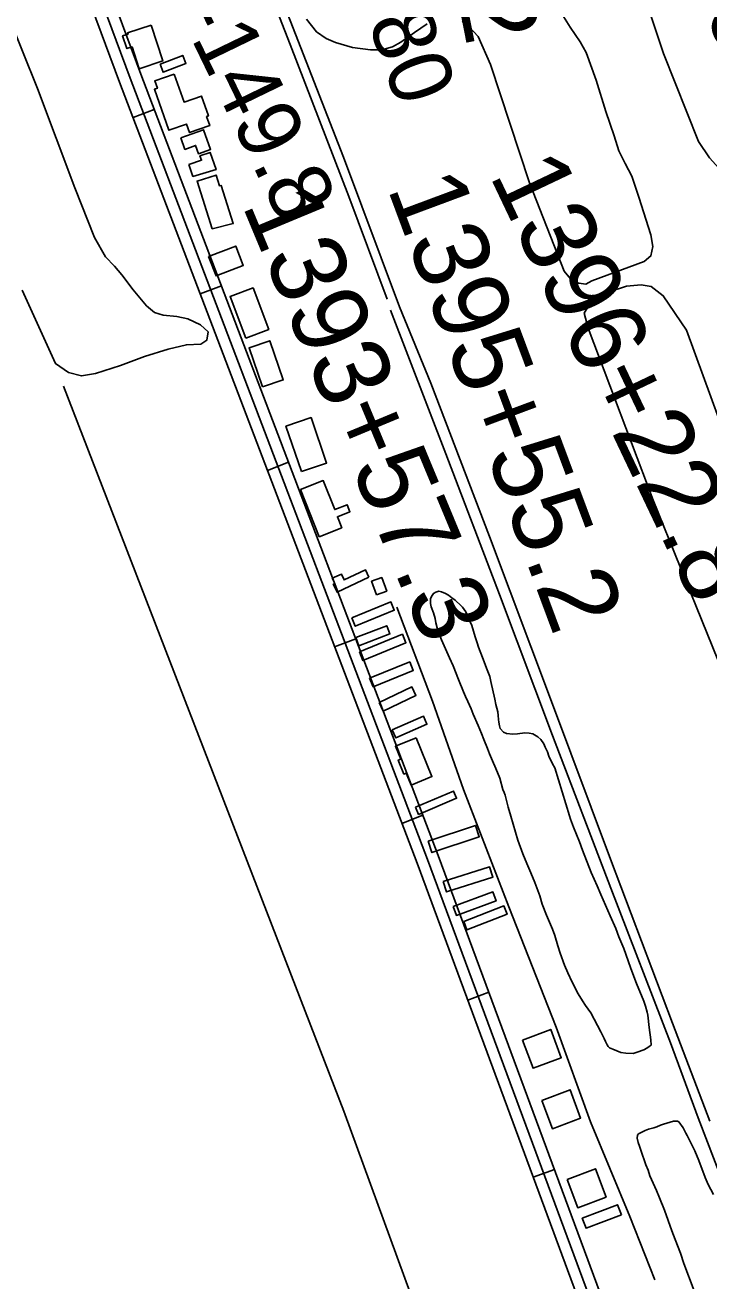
# Model space of a CAD drawing. Extents: x 3445503 to 3483459, y 540493 to 566012.
# Drawn here: x 3474080 to 3474986, y 547604 to 549267 of the extents above; entities that cross this region are included whole.
import ezdxf

# ---------------------------------------------------------------- set-up
doc = ezdxf.new("R2010")
doc.units = 0
for name, color, linetype in [('V-BLDG-OTLN', 7, 'Continuous'), ('V-DTCH-CNTR', 7, 'Continuous'), ('V-RIVR-RANG-IDEN', 7, 'Continuous'), ('V-ROAD-CNTR', 7, 'Continuous'), ('V-SITE-VEGE', 7, 'Continuous'), ('V-SURV-IDEN', 7, 'Continuous'), ('V-TOPO-SHOR', 7, 'Continuous')]:
    doc.layers.add(name, color=color, linetype=linetype)

msp = doc.modelspace()

# ---------------------------------------------------------------- linework, layer by layer
at = {"layer": 'V-BLDG-OTLN'}
for points in [[(3474247.1, 549266.8), (3474262.8, 549219.6), (3474231.5, 549209.2), (3474221.9, 549238), (3474215.1, 549235.8), (3474209.5, 549252.7), (3474216.6, 549255), (3474216.1, 549256.5)], [(3474259, 549215.1), (3474289.1, 549226.7), (3474293.2, 549216.1), (3474263.1, 549204.5)], [(3474277.8, 549202), (3474290.8, 549164.9), (3474313.8, 549173), (3474323.1, 549146.6), (3474320.7, 549145.7), (3474324.8, 549133.9), (3474298.1, 549124.5), (3474294.1, 549135.8), (3474270.5, 549127.6), (3474251.5, 549181.9), (3474255.5, 549183.3), (3474252.1, 549192.9)], [(3474286.6, 549117.7), (3474316.6, 549128.4), (3474325.9, 549102.4), (3474309.9, 549096.6), (3474306, 549107.5), (3474292, 549102.4)], [(3474297.2, 549082.2), (3474313.9, 549088), (3474311.9, 549093.7), (3474325.3, 549098.4), (3474333.3, 549075.6), (3474302.6, 549066.5)], [(3474328.1, 548997.2), (3474308.1, 549060.4), (3474333.2, 549068.4), (3474337.7, 549054.1), (3474339.8, 549054.7), (3474355.9, 549004.2)], [(3474323.2, 548960.4), (3474359.3, 548974.3), (3474369.2, 548948.7), (3474333.1, 548934.8)], [(3474372.4, 548852.5), (3474351.7, 548907.6), (3474382.2, 548919), (3474402.9, 548863.9)], [(3474394.7, 548787.8), (3474376.8, 548839.6), (3474404.2, 548849), (3474422.1, 548797.2)], [(3474446.1, 548675.7), (3474425.6, 548735.8), (3474458.9, 548747.2), (3474479.5, 548687.1)], [(3474469.7, 548589.5), (3474445, 548652), (3474475.2, 548663.9), (3474490.4, 548625.4), (3474506.8, 548631.9), (3474510.5, 548622.5), (3474493.9, 548615.9), (3474499.6, 548601.3)], [(3474535.5, 548535.8), (3474493.4, 548516), (3474488.4, 548526.6), (3474490.3, 548527.5), (3474487, 548534.4), (3474499.1, 548540.1), (3474502.7, 548532.4), (3474530.9, 548545.7)], [(3474545.8, 548512.5), (3474539.1, 548530.5), (3474552.5, 548535.5), (3474559.2, 548517.5)], [(3474512.8, 548482.2), (3474564.6, 548503.2), (3474569.1, 548492.1), (3474517.4, 548471)], [(3474518.1, 548455.9), (3474559.2, 548471.6), (3474563.3, 548460.7), (3474522.2, 548445.1)], [(3474523, 548437), (3474579.8, 548460.3), (3474584.5, 548449), (3474527.6, 548425.6)], [(3474536.4, 548402.3), (3474589.6, 548423.8), (3474594.2, 548412.5), (3474541, 548390.9)], [(3474549, 548370), (3474592.4, 548390.7), (3474597.8, 548379.4), (3474554.4, 548358.6)], [(3474566.5, 548333.9), (3474607.7, 548351.9), (3474612.4, 548341.1), (3474571.2, 548323.2)], [(3474598.3, 548323.1), (3474619, 548271.8), (3474591.4, 548260.7), (3474585, 548276.6), (3474581.8, 548275.3), (3474574.4, 548293.7), (3474577.6, 548295), (3474570.7, 548312)], [(3474597.3, 548231.2), (3474647.7, 548252.8), (3474651.7, 548243.3), (3474601.3, 548221.7)], [(3474613.8, 548186.4), (3474676.7, 548207.3), (3474681.7, 548192.2), (3474618.9, 548171.2)], [(3474634, 548132.8), (3474695.4, 548152.4), (3474699.7, 548138.9), (3474638.3, 548119.3)], [(3474647, 548099.9), (3474699.7, 548119.2), (3474704, 548107.2), (3474651.4, 548088)], [(3474661.1, 548080), (3474714.2, 548100.6), (3474718.5, 548089.7), (3474665.3, 548069.1)], [(3474738.7, 547923.1), (3474752.8, 547885.7), (3474790.2, 547899.7), (3474776.2, 547937.2)], [(3474764.4, 547843.1), (3474778.4, 547805.7), (3474815.9, 547819.8), (3474801.8, 547857.2)], [(3474798, 547738.5), (3474812, 547701.1), (3474849.5, 547715.2), (3474835.4, 547752.6)], [(3474869.8, 547691.8), (3474823.1, 547673.9), (3474818.1, 547687), (3474864.8, 547704.9)]]:
    msp.add_lwpolyline(points, close=True, dxfattribs=at)
at = {"layer": 'V-DTCH-CNTR'}
msp.add_lwpolyline([(3474987.1, 547815.8), (3474937.6, 547945.4), (3474855.2, 548162.5), (3474777.1, 548371.5), (3474695.1, 548589.8), (3474617.7, 548792.8), (3474576.2, 548893.8), (3474502, 549092.1), (3474410.2, 549327.9), (3474326.6, 549537.4), (3474271.5, 549674.3), (3474231.3, 549776.8)], dxfattribs=at)
at = {"layer": 'V-ROAD-CNTR'}
for p, q in [((3474223.3, 549144.6), (3474251.4, 549155.3)), ((3474312.3, 548910.9), (3474340.3, 548921.6)), ((3474401.2, 548677.3), (3474429.2, 548688)), ((3474490.2, 548443.7), (3474518.2, 548454.3)), ((3474579.1, 548210), (3474607.1, 548220.7)), ((3474666.3, 547975.9), (3474694.4, 547986.3)), ((3474753.1, 547741.4), (3474781.2, 547751.8))]:
    msp.add_line(p, q, dxfattribs=at)
for points in [[(3474958, 547230.8), (3474613.3, 548162.3), (3474219.5, 549196.7), (3474020.9, 549730.3)], [(3474972, 547236), (3474627.3, 548167.6), (3474233.6, 549202), (3474034.9, 549735.5)], [(3474864.2, 547440.9), (3474599.3, 548157.1), (3474205.5, 549191.4), (3474006.8, 549725.1)]]:
    msp.add_lwpolyline(points, dxfattribs=at)
at = {"layer": 'V-SITE-VEGE'}
for p, q in [((3474892.5, 547798.8), (3474897, 547801.2)), ((3474897, 547801.2), (3474901.2, 547803.3)), ((3474901.2, 547803.3), (3474905.9, 547805.2)), ((3474905.9, 547805.2), (3474912.8, 547806.8)), ((3474912.8, 547806.8), (3474916.6, 547808)), ((3474916.6, 547808), (3474921.5, 547810.3)), ((3474921.5, 547810.3), (3474925.5, 547811.7)), ((3474925.5, 547811.7), (3474939, 547815.6)), ((3474939, 547815.6), (3474943.9, 547815.7)), ((3474943.9, 547815.7), (3474946, 547814.8)), ((3474946, 547814.8), (3474951.8, 547806.8)), ((3474951.8, 547806.8), (3474955.3, 547799.6)), ((3474955.3, 547799.6), (3474956.7, 547796.8)), ((3474890.8, 547793.3), (3474891.2, 547796.9)), ((3474892, 547787.6), (3474890.8, 547793.3)), ((3474891.2, 547796.9), (3474892.5, 547798.8)), ((3474894, 547782.5), (3474892, 547787.6)), ((3474956.7, 547796.8), (3474958.8, 547793.2)), ((3474958.8, 547793.2), (3474963.1, 547784.5)), ((3474963.1, 547784.5), (3474966.9, 547776.5)), ((3474895.7, 547777.2), (3474894, 547782.5)), ((3474902.2, 547758), (3474895.7, 547777.2)), ((3474966.9, 547776.5), (3474972.2, 547763.4)), ((3474905.1, 547750.8), (3474902.2, 547758)), ((3474907.5, 547743.4), (3474905.1, 547750.8)), ((3474972.2, 547763.4), (3474980.6, 547741)), ((3474916.4, 547723.7), (3474907.5, 547743.4)), ((3474980.6, 547741), (3474984.9, 547731.9)), ((3474920.5, 547714.2), (3474916.4, 547723.7)), ((3474984.9, 547731.9), (3474992, 547718.5)), ((3474926.9, 547697.9), (3474920.5, 547714.2)), ((3474936.7, 547670.4), (3474926.9, 547697.9)), ((3474941, 547658.8), (3474936.7, 547670.4)), ((3474948, 547640.8), (3474941, 547658.8)), ((3474952.7, 547627.3), (3474948, 547640.8)), ((3474966, 547590.9), (3474952.7, 547627.3))]:
    msp.add_line(p, q, dxfattribs=at)
for points in [[(3475059.2, 549403.3), (3475111.7, 549242.1), (3475147.1, 549121.8), (3475151.3, 549106.8), (3475146.8, 549093.9), (3475138.6, 549084.3), (3475113.2, 549072.2), (3475041.3, 549050.3), (3475038.6, 549049.5), (3475030.7, 549050.2), (3475014.9, 549059.8), (3474986.3, 549091.2), (3474971.7, 549112.8), (3474925.8, 549229.5), (3474906.1, 549287.7)], [(3474056.9, 549282), (3474096.9, 549182.8), (3474146.2, 549051.3), (3474172.2, 548985.9), (3474186.9, 548959.9), (3474198.5, 548947.6), (3474208.5, 548936.2), (3474223.3, 548916.3), (3474241.2, 548895.4), (3474251.5, 548886.3), (3474263.2, 548882.9), (3474281.2, 548880.9), (3474295.6, 548878.2), (3474312.4, 548870.2), (3474322.6, 548860.7), (3474320.9, 548849.6), (3474313, 548844.4), (3474293.9, 548843.7), (3474269.7, 548837.7), (3474238.5, 548827.9), (3474206.8, 548816.3), (3474173.6, 548805.6), (3474154.9, 548802.5), (3474137.9, 548806.9), (3474120.7, 548818.8), (3474076.4, 548915.9)], [(3474791.1, 549282), (3474801.8, 549264.2), (3474815.2, 549244.7), (3474823.1, 549230.6), (3474836.3, 549193.8), (3474849.4, 549152.5), (3474860.2, 549120.4), (3474866.6, 549100.3), (3474874.7, 549083.8), (3474883.5, 549066.7), (3474892.9, 549039), (3474908.8, 548989.3), (3474911.6, 548973.9), (3474908.9, 548961.2), (3474900.1, 548953.7), (3474830.8, 548928.2), (3474822.9, 548923.9), (3474813.7, 548925.4), (3474804.5, 548928.2), (3474794.1, 548941.2), (3474748.1, 549058), (3474696.5, 549214.8), (3474680.3, 549251.8), (3474667.8, 549264.9), (3474658.9, 549272.3)], [(3474612.8, 549268.7), (3474595.9, 549257.1), (3474578, 549244.4), (3474566.7, 549238.3), (3474552.6, 549234.1), (3474537.6, 549234), (3474513.9, 549237.2), (3474491.2, 549243.9), (3474479.1, 549249.1), (3474466.3, 549258.2), (3474453.1, 549274.7)], [(3475019.3, 548373), (3474911.7, 548637.9), (3474825.8, 548865.7), (3474820.7, 548885.5), (3474826.8, 548895.6), (3474839.4, 548907), (3474852.5, 548913.3), (3474876.8, 548921.4), (3474896, 548923.2), (3474909.1, 548921), (3474925.3, 548908.6), (3474956.1, 548862.9), (3475032.5, 548653.9)], [(3474617.9, 548496.7), (3474617.1, 548500.9), (3474617.2, 548507.3), (3474618.2, 548510.2), (3474621, 548514.4), (3474624, 548516), (3474628.2, 548517.2), (3474631.8, 548516.6), (3474636.8, 548514.4), (3474640.8, 548512.3), (3474645.4, 548508.6), (3474649.8, 548505.4), (3474657.9, 548498.2), (3474659.6, 548496.1), (3474663.7, 548490.1), (3474665.8, 548485.9), (3474669.3, 548477.9), (3474671.6, 548472.1), (3474676.3, 548457.1), (3474678.7, 548448.9), (3474680.5, 548443.4), (3474686.1, 548429.7), (3474692, 548413.2), (3474695.5, 548404.3), (3474697.1, 548397.9), (3474702.4, 548374.3), (3474703.8, 548367.3), (3474706.2, 548357.6), (3474706.8, 548352.6), (3474707.1, 548347.3), (3474707.5, 548343.9), (3474708.3, 548339.3), (3474709.5, 548335.7)], [(3474709.5, 548335.7), (3474713.7, 548330.8), (3474717.7, 548328.9), (3474726.1, 548327.9), (3474732.4, 548328.3), (3474741.9, 548329.7), (3474747.6, 548329.6), (3474752.7, 548328.5), (3474759.4, 548324.6), (3474763.3, 548321), (3474767.1, 548315.3), (3474769.1, 548311), (3474771.8, 548304.5), (3474773.8, 548298.8), (3474778.8, 548289), (3474781.9, 548283.5), (3474801, 548219.9), (3474802.5, 548215.5), (3474806.4, 548204.9), (3474814.4, 548185.3), (3474818.3, 548174.5), (3474830, 548144.9), (3474837.6, 548127.3), (3474842.7, 548115.9), (3474855.1, 548087.5), (3474862.3, 548070.6), (3474866.6, 548059.6), (3474872.9, 548044.2), (3474881.7, 548019.2), (3474883.8, 548014.1), (3474889.7, 547998.1), (3474899.4, 547974.6), (3474901.6, 547968), (3474904.1, 547960), (3474904.9, 547956.2), (3474906.4, 547939.5), (3474908.8, 547923.3), (3474909.1, 547916.5), (3474906.6, 547914.5), (3474903.6, 547912.4), (3474899.4, 547910.3), (3474890.9, 547907), (3474885.2, 547905.4), (3474875.5, 547905.5), (3474869, 547906.4), (3474858.5, 547910.8), (3474854.3, 547912.9), (3474852.2, 547914.4), (3474850.8, 547916.7), (3474848.7, 547921), (3474847.1, 547925.2), (3474844.4, 547930.5), (3474842.7, 547934.1), (3474829.3, 547959.1), (3474825.8, 547963.8), (3474822.2, 547968.8), (3474818.3, 547975), (3474812.7, 547984.1), (3474804.7, 547999.6), (3474798.9, 548012.1), (3474794.4, 548022.2), (3474788.8, 548037.9), (3474785.8, 548047.6), (3474781.5, 548061.7), (3474778.6, 548069.8), (3474770.6, 548088.6), (3474765.1, 548103), (3474761.8, 548113.8), (3474755.3, 548131.7), (3474750.1, 548144.6), (3474744.6, 548156.7), (3474739.4, 548169.6), (3474732.7, 548187.6), (3474723.5, 548219.3), (3474720.1, 548231.5), (3474715.8, 548247.4), (3474714.8, 548250.7), (3474712.9, 548254.8), (3474708.9, 548270), (3474703.5, 548282.7), (3474699, 548292.6), (3474695.1, 548302.1), (3474692.6, 548309.3), (3474687.9, 548320.9), (3474684.4, 548328.8), (3474680.1, 548339.6), (3474673.7, 548354.4), (3474671.1, 548361.4), (3474666.3, 548371.1), (3474663.4, 548378.1), (3474660.8, 548384), (3474654.2, 548400.3), (3474647, 548418.5), (3474642.3, 548429.3), (3474631.6, 548453), (3474628.1, 548461.6), (3474626.2, 548467.1), (3474624.2, 548475.6), (3474623.2, 548481.1), (3474621.2, 548488.7), (3474617.9, 548496.7)]]:
    msp.add_lwpolyline(points, dxfattribs=at)
at = {"layer": 'V-TOPO-SHOR'}
for points in [[(3474269, 549653.6), (3474357.5, 549430.5), (3474431.3, 549241.1), (3474509, 549039.8), (3474559.7, 548903.9)], [(3474564.3, 548889.6), (3474637.3, 548699.4), (3474708.4, 548512.8), (3474778.7, 548326.2), (3474855.9, 548124.1), (3474934.7, 547919.2), (3474971.6, 547820.2)], [(3474670.6, 547368.5), (3474502.3, 547828.8), (3474131.1, 548788.9)], [(3474829, 547814.9), (3474783.4, 547940.1), (3474720.7, 548099.4), (3474660.7, 548254.8), (3474619.7, 548371.6), (3474572.4, 548496.4)], [(3475659.9, 546017.7), (3475620, 546122.4), (3475559, 546279.9), (3475491.7, 546456.9), (3475440.4, 546595.6), (3475387.2, 546732.1), (3475322.5, 546906), (3475244.8, 547105.9), (3475186.6, 547255.6), (3475124.5, 547422.2), (3475073.8, 547553.2), (3474971.6, 547820.2)], [(3474829, 547814.9), (3474880.8, 547689.3), (3474914.1, 547605.7)]]:
    msp.add_lwpolyline(points, dxfattribs=at)

# ---------------------------------------------------------------- texts
at = {"layer": 'V-RIVR-RANG-IDEN'}
for s, rotation, p in [('U-080', 289.3916, (3474474.4, 549440.5)), ('R-149.8', 295.8501, (3474248.5, 549355.3))]:
    msp.add_text(s, height=83, rotation=rotation, dxfattribs=at).set_placement(p)
at = {"layer": 'V-SURV-IDEN'}
for s, rotation, p in [('1398+79.2', 281.2389, (3474542, 549860.7)), ('1400+01.3', 293.2499, (3474830.4, 549632.3)), ('1396+22.8', 295.4176, (3474694.6, 549068.6)), ('1395+55.2', 290.4255, (3474559.5, 549051.5)), ('1393+57.3', 292.598, (3474367.1, 549029.2))]:
    msp.add_text(s, height=100, rotation=rotation, dxfattribs=at).set_placement(p)

doc.saveas('drawing.dxf')
